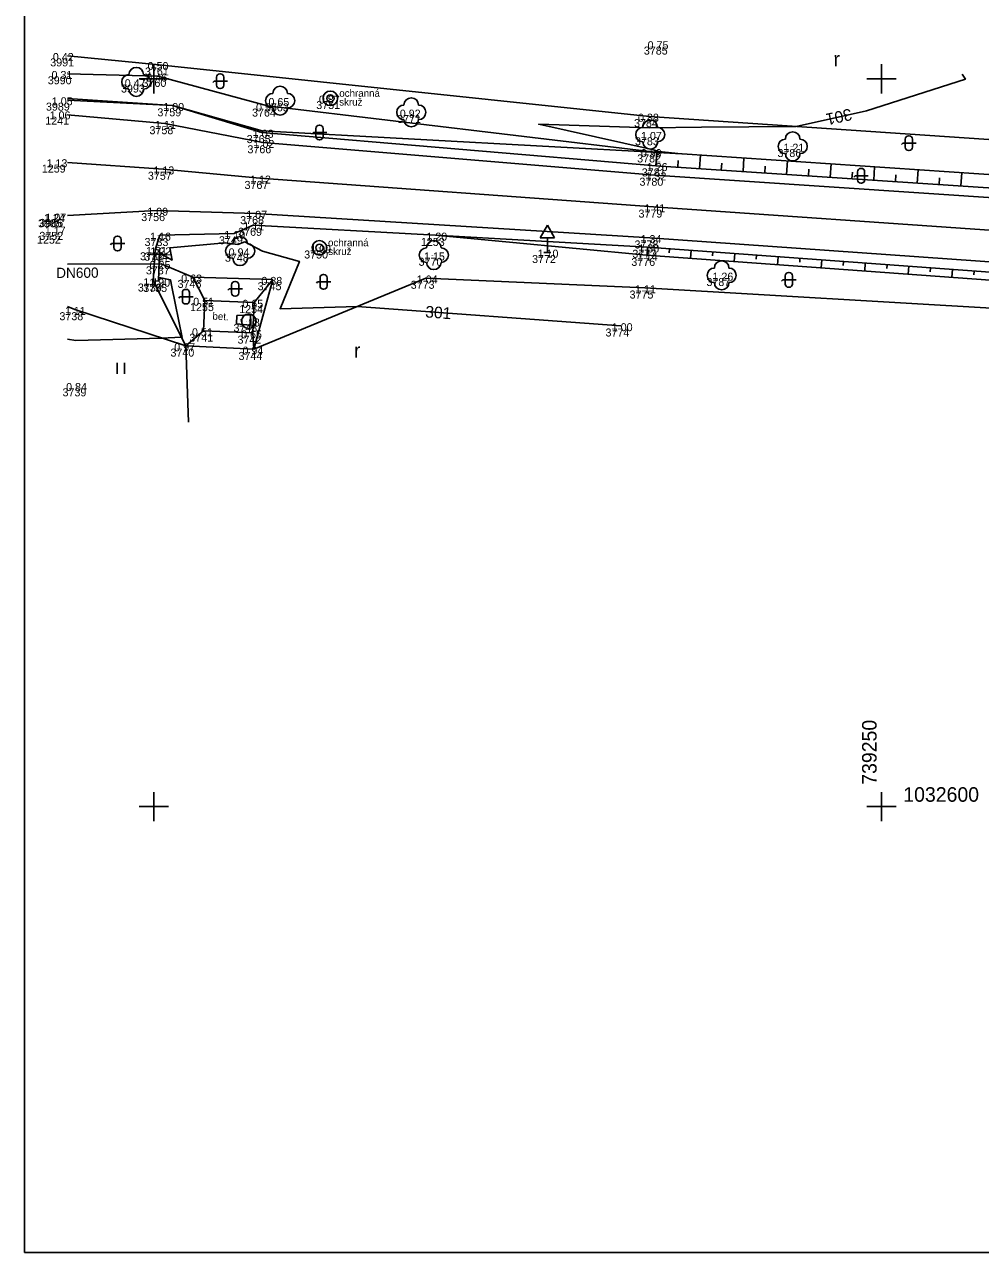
# Model space of a CAD drawing. Extents: x -740053 to -737517, y -1033516 to -1032476.
# Drawn here: x -739308.9 to -739243.2, y -1032630.6 to -1032546.3 of the extents above; entities that cross this region are included whole.
import ezdxf

# ---------------------------------------------------------------- set-up
doc = ezdxf.new("R2010")
doc.units = 0
for name, color, linetype in [('bod-cislo', 7, 'Continuous'), ('bod-oznac', 7, 'Continuous'), ('bod-vyska', 7, 'Continuous'), ('bod-vyska100', 7, 'Continuous'), ('Contours', 7, 'Continuous'), ('Contours text', 7, 'Continuous'), ('ctv-sit', 7, 'Continuous'), ('dopr-zariz', 7, 'Continuous'), ('Kanalizace', 7, 'Continuous'), ('nazvy-bud-povr', 7, 'Continuous'), ('objekty-na-vodovodu', 7, 'Continuous'), ('osa-komunikace', 7, 'Continuous'), ('Popis-Kanalizace', 7, 'Continuous'), ('Predmety bez rozlišeni', 7, 'Continuous'), ('Rozhrani-ploch', 7, 'Continuous'), ('rozhraní kultůr', 7, 'Continuous'), ('silnice', 7, 'Continuous'), ('Technické šrafy', 7, 'Continuous'), ('Terenni-hrana', 7, 'Continuous'), ('Znacky-kultury', 7, 'Continuous')]:
    doc.layers.add(name, color=color, linetype=linetype)

# ---------------------------------------------------------------- blocks, each defined once
blk = doc.blocks.new('po_kansa')
blk.add_circle((0, 0), 1)
blk = doc.blocks.new('POINT_DISPLAY')
blk.add_line((0, 0), (0, 0))
blk = doc.blocks.new('p_strom')
for centre, start, end in [((0, 1), 0, 180), ((-1, 0), 90, 270), ((1, 0), 270, 90), ((0, -1), 180, 0)]:
    blk.add_arc(centre, 1, start, end)
at = {"rotation": -180}
blk.add_blockref('POINT_DISPLAY', (0, 0), dxfattribs=at)
blk = doc.blocks.new('vo_soupe')
blk.add_circle((0, 0), 0.5)
blk = doc.blocks.new('d_znacka')
for p, q in [((-1, 2), (0, 3.73)), ((0, 3.73), (1, 2)), ((-1, 2), (1, 2)), ((0, 0), (0, 2)), ((-0.5, 0), (0.5, 0))]:
    blk.add_line(p, q)
blk = doc.blocks.new('p_neplod')
for p, q in [((-0.82, 0), (-0.99, -0.18)), ((1, 0), (-0.82, 0)), ((-0.49, 0.56), (-0.49, -0.55)), ((0.05, 1.01), (-0.04, 1.01)), ((0.5, -0.55), (0.5, 0.56)), ((-0.04, -1), (0.05, -1))]:
    blk.add_line(p, q)
for centre, start, end in [((-0.04, 0.56), 90, 180), ((0.05, 0.56), 0, 90), ((-0.04, -0.55), 180, 270), ((0.05, -0.55), 270, 0)]:
    blk.add_arc(centre, 0.45, start, end)
blk = doc.blocks.new('p_louka')
for p, q in [((-0.47, 0.72), (-0.47, -0.78)), ((0.53, 0.72), (0.53, -0.78))]:
    blk.add_line(p, q)
blk = doc.blocks.new('p_orna')
blk.add_text('r', height=2).set_placement((0, 0))
blk = doc.blocks.new('ctvsit')
for p, q in [((0, -2), (0, 2)), ((2, 0), (-2, 0))]:
    blk.add_line(p, q)

msp = doc.modelspace()

# ---------------------------------------------------------------- linework, layer by layer
at = {"layer": 'Contours'}
for points in [[(-739244.461, -1032549.689), (-739244.232, -1032550.011), (-739251.035, -1032552.195), (-739255.866, -1032553.267), (-739262.362, -1032553.329), (-739265.908, -1032553.369), (-739273.553, -1032553.116), (-739265.759, -1032554.863), (-739265.302, -1032554.993), (-739263.763, -1032555.144), (-739265.731, -1032555.046), (-739272.448, -1032554.678), (-739292.546, -1032553.566), (-739298.72, -1032551.84), (-739305.934, -1032551.343), (-739305.94, -1032551.343)], [(-739299.577, -1032561.973), (-739298.75, -1032562.457), (-739298.905, -1032561.619), (-739295.092, -1032561.268), (-739294.227, -1032561.38), (-739293.752, -1032561.202), (-739292.524, -1032561.839), (-739289.991, -1032562.544), (-739291.32, -1032565.792), (-739286.028, -1032565.646), (-739267.9, -1032566.97)], [(-739305.94, -1032567.878), (-739305.359, -1032567.981), (-739299.445, -1032567.814), (-739298.115, -1032567.74), (-739298.054, -1032567.771), (-739298.759, -1032564.29), (-739298.852, -1032563.812), (-739299.642, -1032563.655)], [(-739293.385, -1032566.925), (-739293.355, -1032566.213), (-739294.292, -1032566.266), (-739294.316, -1032566.83), (-739293.385, -1032566.925)]]:
    msp.add_lwpolyline(points, dxfattribs=at)
at = {"layer": 'Kanalizace'}
msp.add_line((-739299.5, -1032562.7), (-739305.94, -1032562.743), dxfattribs=at)
at = {"layer": 'osa-komunikace'}
for p, q in [((-739305.94, -1032555.758), (-739299.36, -1032556.2)), ((-739299.36, -1032556.2), (-739292.72, -1032556.83)), ((-739292.72, -1032556.83), (-739265.66, -1032558.8)), ((-739265.66, -1032558.8), (-739230.45, -1032561.23))]:
    msp.add_line(p, q, dxfattribs=at)
at = {"layer": 'Predmety bez rozlišeni'}
for p, q in [((-739308.885, -1032630.632), (-739308.885, -1032482.132)), ((-739203.885, -1032630.632), (-739308.885, -1032630.632))]:
    msp.add_line(p, q, dxfattribs=at)
at = {"layer": 'Rozhrani-ploch'}
for p, q in [((-739300.05, -1032563.88), (-739299.9, -1032561.73)), ((-739299.9, -1032561.73), (-739299.6, -1032561.76)), ((-739299.6, -1032561.76), (-739299.68, -1032563.91)), ((-739299.68, -1032563.91), (-739300.05, -1032563.88)), ((-739296.59, -1032567.32), (-739296.503, -1032565.222)), ((-739296.503, -1032565.222), (-739293.113, -1032565.362)), ((-739293.113, -1032565.362), (-739293.2, -1032567.46)), ((-739296.59, -1032567.32), (-739293.2, -1032567.46))]:
    msp.add_line(p, q, dxfattribs=at)
for centre in [(-739287.87, -1032551.34), (-739288.62, -1032561.61)]:
    msp.add_circle(centre, 0.5, dxfattribs=at)
at = {"layer": 'rozhraní kultůr'}
for p, q in [((-739299.64, -1032549.03), (-739305.94, -1032548.43)), ((-739265.94, -1032552.58), (-739299.64, -1032549.03)), ((-739265.94, -1032552.58), (-739229.84, -1032555.04)), ((-739281.3, -1032563.69), (-739293.12, -1032568.58)), ((-739281.3, -1032563.69), (-739266.26, -1032564.36)), ((-739266.26, -1032564.36), (-739230.44, -1032566.46)), ((-739305.44, -1032565.85), (-739305.94, -1032565.652)), ((-739297.81, -1032568.35), (-739305.44, -1032565.85)), ((-739297.61, -1032573.58), (-739297.81, -1032568.35))]:
    msp.add_line(p, q, dxfattribs=at)
at = {"layer": 'silnice'}
for p, q in [((-739299.25, -1032553.07), (-739305.94, -1032552.468)), ((-739299.25, -1032553.07), (-739292.52, -1032554.38)), ((-739292.52, -1032554.38), (-739265.58, -1032556.61)), ((-739265.58, -1032556.61), (-739230.41, -1032558.96)), ((-739299.82, -1032559.04), (-739305.94, -1032559.39)), ((-739299.82, -1032559.04), (-739293.02, -1032559.25)), ((-739293.02, -1032559.25), (-739265.92, -1032560.92)), ((-739265.92, -1032560.92), (-739230.56, -1032563.42))]:
    msp.add_line(p, q, dxfattribs=at)
at = {"layer": 'Technické šrafy'}
for p, q in [((-739265.5, -1032555.97), (-739265.438, -1032555.031)), ((-739262.507, -1032556.168), (-739262.445, -1032555.234)), ((-739264.003, -1032556.069), (-739263.972, -1032555.601)), ((-739261.01, -1032556.267), (-739260.979, -1032555.801)), ((-739259.513, -1032556.366), (-739259.452, -1032555.438)), ((-739258.016, -1032556.465), (-739257.986, -1032556.002)), ((-739256.52, -1032556.564), (-739256.459, -1032555.641)), ((-739253.526, -1032556.762), (-739253.466, -1032555.845)), ((-739250.533, -1032556.96), (-739250.472, -1032556.048)), ((-739255.023, -1032556.663), (-739254.992, -1032556.203)), ((-739252.029, -1032556.861), (-739251.999, -1032556.404)), ((-739249.036, -1032557.059), (-739249.006, -1032556.604)), ((-739247.539, -1032557.158), (-739247.479, -1032556.252)), ((-739246.042, -1032557.256), (-739246.013, -1032556.805)), ((-739244.546, -1032557.355), (-739244.486, -1032556.456)), ((-739266.07, -1032561.56), (-739266.111, -1032562.122)), ((-739264.574, -1032561.67), (-739264.595, -1032561.95)), ((-739263.078, -1032561.78), (-739263.119, -1032562.338)), ((-739261.582, -1032561.89), (-739261.603, -1032562.168)), ((-739260.086, -1032562), (-739260.127, -1032562.554)), ((-739258.59, -1032562.111), (-739258.611, -1032562.386)), ((-739257.094, -1032562.221), (-739257.135, -1032562.77)), ((-739255.598, -1032562.331), (-739255.618, -1032562.604)), ((-739254.102, -1032562.441), (-739254.142, -1032562.986)), ((-739252.606, -1032562.551), (-739252.626, -1032562.822)), ((-739251.11, -1032562.661), (-739251.15, -1032563.201)), ((-739249.615, -1032562.771), (-739249.634, -1032563.04)), ((-739248.119, -1032562.881), (-739248.158, -1032563.417)), ((-739246.623, -1032562.991), (-739246.642, -1032563.258)), ((-739245.127, -1032563.102), (-739245.166, -1032563.633)), ((-739243.631, -1032563.212), (-739243.65, -1032563.476))]:
    msp.add_line(p, q, dxfattribs=at)
at = {"layer": 'Terenni-hrana'}
for p, q in [((-739299.73, -1032549.82), (-739305.94, -1032549.648)), ((-739299.73, -1032549.82), (-739292.19, -1032551.86)), ((-739298.72, -1032551.84), (-739305.94, -1032551.472)), ((-739298.72, -1032551.84), (-739292.57, -1032553.68)), ((-739292.19, -1032551.86), (-739265.74, -1032555.01)), ((-739292.57, -1032553.68), (-739265.5, -1032555.97)), ((-739265.74, -1032555.01), (-739230.16, -1032557.43)), ((-739265.5, -1032555.97), (-739230.26, -1032558.3)), ((-739294.49, -1032560.63), (-739293.17, -1032560.05)), ((-739293.17, -1032560.05), (-739280.642, -1032560.748)), ((-739299.9, -1032561.73), (-739299.59, -1032560.75)), ((-739299.59, -1032560.75), (-739294.49, -1032560.63)), ((-739266.14, -1032562.12), (-739280.642, -1032560.748)), ((-739280.642, -1032560.748), (-739266.07, -1032561.56)), ((-739266.07, -1032561.56), (-739230.61, -1032564.17)), ((-739299.5, -1032562.7), (-739297.32, -1032563.63)), ((-739266.14, -1032562.12), (-739230.38, -1032564.7)), ((-739291.82, -1032563.79), (-739297.32, -1032563.63)), ((-739296.503, -1032565.222), (-739297.32, -1032563.63)), ((-739300.05, -1032563.88), (-739297.81, -1032568.35)), ((-739293.12, -1032568.58), (-739291.82, -1032563.79)), ((-739291.82, -1032563.79), (-739293.113, -1032565.362)), ((-739297.81, -1032568.35), (-739296.59, -1032567.32)), ((-739293.12, -1032568.58), (-739293.2, -1032567.46)), ((-739297.81, -1032568.35), (-739293.12, -1032568.58))]:
    msp.add_line(p, q, dxfattribs=at)

# ---------------------------------------------------------------- block references
at = {"layer": 'bod-oznac'}
for p in [(-739265.28, -1032547.6), (-739299.64, -1032549.03), (-739301.21, -1032550.21), (-739299.73, -1032549.82), (-739298.72, -1032551.84), (-739292.19, -1032551.86), (-739291.32, -1032551.5), (-739287.87, -1032551.34), (-739282.31, -1032552.3), (-739265.94, -1032552.58), (-739299.25, -1032553.07), (-739292.57, -1032553.68), (-739292.52, -1032554.38), (-739265.89, -1032553.83), (-739265.74, -1032555.01), (-739256.1, -1032554.64), (-739265.5, -1032555.97), (-739299.36, -1032556.2), (-739292.72, -1032556.83), (-739265.58, -1032556.61), (-739299.82, -1032559.04), (-739293.02, -1032559.25), (-739265.66, -1032558.8), (-739293.17, -1032560.05), (-739299.59, -1032560.75), (-739294.49, -1032560.63), (-739280.642, -1032560.748), (-739265.92, -1032560.92), (-739299.9, -1032561.73), (-739299.6, -1032561.76), (-739294.07, -1032561.83), (-739288.62, -1032561.61), (-739272.96, -1032561.92), (-739266.07, -1032561.56), (-739299.5, -1032562.7), (-739280.76, -1032562.11), (-739266.14, -1032562.12), (-739297.32, -1032563.63), (-739281.3, -1032563.69), (-739260.98, -1032563.5), (-739300.05, -1032563.88), (-739299.68, -1032563.91), (-739291.82, -1032563.79), (-739266.26, -1032564.36), (-739296.503, -1032565.222), (-739293.113, -1032565.362), (-739305.44, -1032565.85), (-739293.48, -1032566.65), (-739267.9, -1032566.97), (-739296.59, -1032567.32), (-739293.2, -1032567.46), (-739297.81, -1032568.35), (-739293.12, -1032568.58), (-739305.24, -1032571.08)]:
    msp.add_blockref('POINT_DISPLAY', p, dxfattribs=at)
at = {"layer": 'ctv-sit', "xscale": 0.5, "yscale": 0.5, "rotation": 180}
for p in [(-739300, -1032550), (-739250, -1032550), (-739300, -1032600), (-739250, -1032600)]:
    msp.add_blockref('ctvsit', p, dxfattribs=at)
at = {"layer": 'dopr-zariz', "xscale": 0.5, "yscale": 0.5}
msp.add_blockref('d_znacka', (-739272.96, -1032561.92), dxfattribs=at)
at = {"layer": 'objekty-na-vodovodu', "xscale": 0.5, "yscale": 0.5}
for name, p in [('vo_soupe', (-739287.87, -1032551.34)), ('vo_soupe', (-739288.62, -1032561.61)), ('po_kansa', (-739293.48, -1032566.65))]:
    msp.add_blockref(name, p, dxfattribs=at)
at = {"layer": 'Znacky-kultury', "xscale": 0.5, "yscale": 0.5}
for name, p in [('p_orna', (-739253.296, -1032549.138)), ('p_strom', (-739301.21, -1032550.21)), ('p_neplod', (-739295.44, -1032550.164)), ('p_strom', (-739291.32, -1032551.5)), ('p_strom', (-739282.31, -1032552.3)), ('p_neplod', (-739288.623, -1032553.684)), ('p_strom', (-739265.89, -1032553.83)), ('p_strom', (-739256.1, -1032554.64)), ('p_neplod', (-739248.121, -1032554.419)), ('p_neplod', (-739251.406, -1032556.657)), ('p_neplod', (-739302.493, -1032561.319)), ('p_strom', (-739294.07, -1032561.83)), ('p_strom', (-739280.76, -1032562.11)), ('p_strom', (-739260.98, -1032563.5)), ('p_neplod', (-739288.337, -1032563.951)), ('p_neplod', (-739256.369, -1032563.82)), ('p_neplod', (-739297.797, -1032564.967)), ('p_neplod', (-739294.417, -1032564.429)), ('p_orna', (-739286.246, -1032569.161)), ('p_louka', (-739302.289, -1032569.875))]:
    msp.add_blockref(name, p, dxfattribs=at)

# ---------------------------------------------------------------- texts
at = {"layer": 'bod-cislo'}
for s, p in [('3785', (-739266.328, -1032548.333)), ('3991', (-739307.119, -1032549.143)), ('3761', (-739300.609, -1032549.763)), ('3990', (-739307.288, -1032550.373)), ('3760', (-739300.778, -1032550.553)), ('3993', (-739302.258, -1032550.943)), ('3989', (-739307.415, -1032552.183)), ('3763', (-739292.368, -1032552.233)), ('3751', (-739288.839, -1032552.073)), ('1241', (-739307.46, -1032553.148)), ('3759', (-739299.755, -1032552.573)), ('3764', (-739293.251, -1032552.593)), ('3771', (-739283.279, -1032553.033)), ('3784', (-739267.001, -1032553.313)), ('3758', (-739300.298, -1032553.803)), ('3765', (-739293.618, -1032554.413)), ('3783', (-739266.938, -1032554.563)), ('3766', (-739293.568, -1032555.113)), ('3782', (-739266.788, -1032555.743)), ('3786', (-739257.148, -1032555.373)), ('1259', (-739307.698, -1032556.44)), ('3781', (-739266.469, -1032556.703)), ('3757', (-739300.408, -1032556.933)), ('3780', (-739266.628, -1032557.343)), ('3767', (-739293.768, -1032557.563)), ('3756', (-739300.868, -1032559.773)), ('3768', (-739294.068, -1032559.983)), ('3779', (-739266.695, -1032559.533)), ('3985', (-739307.958, -1032560.203)), ('3986', (-739307.868, -1032560.173)), ('3769', (-739294.205, -1032560.783)), ('1252', (-739308.028, -1032561.323)), ('3752', (-739307.868, -1032561.063)), ('3733', (-739300.638, -1032561.483)), ('3749', (-739295.525, -1032561.363)), ('1253', (-739281.65, -1032561.481)), ('3778', (-739266.968, -1032561.653)), ('3732', (-739300.948, -1032562.463)), ('3734', (-739300.661, -1032562.493)), ('3748', (-739295.118, -1032562.563)), ('3750', (-739289.668, -1032562.343)), ('3777', (-739267.118, -1032562.293)), ('3737', (-739300.548, -1032563.433)), ('3770', (-739281.808, -1032562.843)), ('3772', (-739274.008, -1032562.653)), ('3776', (-739267.188, -1032562.853)), ('3787', (-739262.028, -1032564.233)), ('3736', (-739301.098, -1032564.613)), ('3735', (-739300.728, -1032564.643)), ('3746', (-739298.368, -1032564.363)), ('3745', (-739292.868, -1032564.523)), ('3773', (-739282.348, -1032564.423)), ('3775', (-739267.308, -1032565.093)), ('1255', (-739297.511, -1032565.955)), ('3738', (-739306.488, -1032566.583)), ('1254', (-739294.134, -1032566.095)), ('3743', (-739294.528, -1032567.383)), ('3741', (-739297.559, -1032568.053)), ('3742', (-739294.248, -1032568.193)), ('3774', (-739268.961, -1032567.703)), ('3740', (-739298.858, -1032569.083)), ('3744', (-739294.181, -1032569.313)), ('3739', (-739306.275, -1032571.813))]:
    msp.add_text(s, height=0.55, dxfattribs=at).set_placement(p)
at = {"layer": 'bod-vyska'}
for s, p in [('0 75', (-739266.069, -1032547.967)), ('0 42', (-739306.939, -1032548.777)), ('0 50', (-739300.429, -1032549.397)), ('0 31', (-739307.029, -1032550.007)), ('0 47', (-739301.999, -1032550.577)), ('0 46', (-739300.519, -1032550.187)), ('1 05', (-739307.012, -1032551.817)), ('1 00', (-739299.352, -1032552.207)), ('0 55', (-739292.979, -1032552.227)), ('0 65', (-739292.122, -1032551.867)), ('0 87', (-739288.659, -1032551.707)), ('1 06', (-739307.162, -1032552.782)), ('0 92', (-739283.099, -1032552.667)), ('0 88', (-739266.729, -1032552.947)), ('1 11', (-739299.921, -1032553.437)), ('1 03', (-739293.202, -1032554.047)), ('1 02', (-739293.152, -1032554.747)), ('1 07', (-739266.522, -1032554.197)), ('1 21', (-739256.732, -1032555.007)), ('0 99', (-739266.529, -1032555.377)), ('1 13', (-739307.374, -1032556.074)), ('1 13', (-739300.031, -1032556.567)), ('1 26', (-739266.132, -1032556.337)), ('1 12', (-739293.391, -1032557.197)), ('1 32', (-739266.212, -1032556.977)), ('1 41', (-739266.292, -1032559.167)), ('1 24', (-739307.542, -1032559.837)), ('1 07', (-739307.452, -1032559.807)), ('1 09', (-739300.452, -1032559.407)), ('1 07', (-739293.652, -1032559.617)), ('1 17', (-739307.491, -1032560.697)), ('1 11', (-739293.841, -1032560.417)), ('1 16', (-739300.261, -1032561.117)), ('1 10', (-739295.161, -1032560.997)), ('1 20', (-739281.274, -1032561.115)), ('1 34', (-739266.552, -1032561.287)), ('1 21', (-739300.532, -1032562.097)), ('1 22', (-739300.232, -1032562.127)), ('0 94', (-739294.859, -1032562.197)), ('1 09', (-739289.252, -1032561.977)), ('1 15', (-739281.431, -1032562.477)), ('1 10', (-739273.631, -1032562.287)), ('1 14', (-739266.811, -1032562.487)), ('1 30', (-739266.702, -1032561.927)), ('0 25', (-739300.289, -1032563.067)), ('1 19', (-739300.721, -1032564.247)), ('1 20', (-739300.312, -1032564.277)), ('0 63', (-739298.122, -1032563.997)), ('0 88', (-739292.609, -1032564.157)), ('1 04', (-739281.932, -1032564.057)), ('1 26', (-739261.612, -1032563.867)), ('1 11', (-739266.931, -1032564.727)), ('0 51', (-739297.292, -1032565.589)), ('0 65', (-739293.915, -1032565.729)), ('1 11', (-739306.111, -1032566.217)), ('1 18', (-739294.151, -1032567.017)), ('1 00', (-739268.532, -1032567.337)), ('0 51', (-739297.379, -1032567.687)), ('0 65', (-739294.002, -1032567.827)), ('0 97', (-739298.599, -1032568.717)), ('0 94', (-739293.909, -1032568.947)), ('0 84', (-739306.029, -1032571.447))]:
    msp.add_text(s, height=0.55, dxfattribs=at).set_placement(p)
at = {"layer": 'bod-vyska100'}
for s, p in [('300 75', (-739265.447, -1032547.633)), ('300 50', (-739299.807, -1032549.063)), ('300 47', (-739301.377, -1032550.243)), ('300 46', (-739299.897, -1032549.853)), ('301 00', (-739298.88, -1032551.873)), ('300 55', (-739292.357, -1032551.893)), ('300 65', (-739291.488, -1032551.533)), ('300 87', (-739288.037, -1032551.373)), ('300 92', (-739282.477, -1032552.333)), ('300 88', (-739266.107, -1032552.613)), ('301 11', (-739299.413, -1032553.103)), ('301 03', (-739292.73, -1032553.713)), ('301 02', (-739292.68, -1032554.413)), ('301 07', (-739266.05, -1032553.863)), ('300 99', (-739265.907, -1032555.043)), ('301 21', (-739256.26, -1032554.673)), ('301 26', (-739265.66, -1032556.003)), ('301 13', (-739299.523, -1032556.233)), ('301 12', (-739292.883, -1032556.863)), ('301 32', (-739265.74, -1032556.643)), ('301 09', (-739299.98, -1032559.073)), ('301 07', (-739293.18, -1032559.283)), ('301 41', (-739265.82, -1032558.833)), ('301 11', (-739293.333, -1032560.083)), ('301 16', (-739299.753, -1032560.783)), ('301 10', (-739294.653, -1032560.663)), ('301 20', (-739280.802, -1032560.781)), ('301 34', (-739266.08, -1032560.953)), ('301 21', (-739300.06, -1032561.763)), ('301 22', (-739299.76, -1032561.793)), ('300 94', (-739294.237, -1032561.863)), ('301 09', (-739288.78, -1032561.643)), ('301 10', (-739273.123, -1032561.953)), ('301 30', (-739266.23, -1032561.593)), ('300 25', (-739299.667, -1032562.733)), ('301 15', (-739280.923, -1032562.143)), ('301 14', (-739266.303, -1032562.153)), ('300 63', (-739297.488, -1032563.663)), ('301 04', (-739281.46, -1032563.723)), ('301 26', (-739261.14, -1032563.533)), ('301 19', (-739300.213, -1032563.913)), ('301 20', (-739299.84, -1032563.943)), ('300 88', (-739291.987, -1032563.823)), ('301 11', (-739266.423, -1032564.393)), ('300 51', (-739296.67, -1032565.255)), ('300 65', (-739293.281, -1032565.395)), ('301 11', (-739305.603, -1032565.883)), ('301 18', (-739293.643, -1032566.683)), ('301 00', (-739268.06, -1032567.003)), ('300 51', (-739296.757, -1032567.353)), ('300 65', (-739293.368, -1032567.493)), ('300 97', (-739297.977, -1032568.383)), ('300 94', (-739293.287, -1032568.613)), ('300 84', (-739305.407, -1032571.113))]:
    msp.add_text(s, height=0.05, dxfattribs=at).set_placement(p)
at = {"layer": 'Contours text'}
for rotation, p in [(192.50524, (-739252.133, -1032552.029)), (355.82275, (-739281.368, -1032566.387))]:
    msp.add_text('301', height=0.8, rotation=rotation, dxfattribs=at).set_placement(p)
at = {"layer": 'ctv-sit'}
msp.add_text('739250', height=1, rotation=90, dxfattribs=at).set_placement((-739250.333, -1032598.5))
msp.add_text('1032600', height=1, dxfattribs=at).set_placement((-739248.5, -1032599.667))
at = {"layer": 'nazvy-bud-povr'}
for s, p in [('ochranná', (-739287.255, -1032551.233)), ('skruž', (-739287.262, -1032551.836)), ('ochranná', (-739288.031, -1032561.498)), ('skruž', (-739288.012, -1032562.106))]:
    msp.add_text(s, height=0.5, dxfattribs=at).set_placement(p)
msp.add_text('bet.', height=0.5, rotation=357.09697, dxfattribs=at).set_placement((-739295.982, -1032566.541))
at = {"layer": 'Popis-Kanalizace'}
msp.add_text('DN600', height=0.7, rotation=0.38416, dxfattribs=at).set_placement((-739306.71, -1032563.682))

doc.saveas('drawing.dxf')
